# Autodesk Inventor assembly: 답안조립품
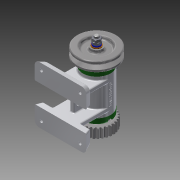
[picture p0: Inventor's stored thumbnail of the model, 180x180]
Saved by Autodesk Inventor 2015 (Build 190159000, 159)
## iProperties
Created: 2016-07
Part Number: 답안조립품
Document SubType Name: Assembly
Designer: owner
Author: owner
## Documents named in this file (16)
- C:\Users\owner\Documents\460707V1007\460707V1007\답안조립품.iam
- C:\Users\owner\Documents\460707V1007\460707V1007\답안본체.ipt
- C:\Users\owner\Documents\460707V1007\460707V1007\너트 M 8.ipt
- C:\Users\owner\Documents\460707V1007\460707V1007\베어링 15 x 32 x 9.ipt
- C:\Users\owner\Documents\460707V1007\460707V1007\스프링와셔 8.ipt
- C:\Users\owner\Documents\460707V1007\460707V1007\오일 실 15 25 7.ipt
- C:\Users\owner\Documents\460707V1007\460707V1007\와셔 8x17.ipt
- C:\Users\owner\Documents\460707V1007\460707V1007\커버.ipt
- C:\Users\owner\Documents\460707V1007\460707V1007\키 3 x 3 x 12.ipt
- C:\Users\owner\Documents\460707V1007\460707V1007\V벨트풀리.ipt
- C:\Users\owner\Documents\460707V1007\460707V1007\니플 M 6 x 0.75.ipt
- C:\Users\owner\Documents\460707V1007\460707V1007\볼트 M 6 x 8.ipt
- C:\Users\owner\Documents\460707V1007\460707V1007\스퍼기어.ipt
- C:\Users\owner\Documents\460707V1007\460707V1007\와셔 6x11.5.ipt
- C:\Users\owner\Documents\460707V1007\460707V1007\축.ipt
- C:\Users\owner\Documents\460707V1007\460707V1007\볼트 M4 x 12.ipt
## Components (11 placed, 3 different names)
1. KS B 2023 6002 - 15 x 32 x 9:1
2. KS B 2023 6002 - 15 x 32 x 9:2
3. V벨트풀리:1 — 각도:3
4. ISO 4762 M4 x 12:1
5. ISO 4762 M4 x 12:3
6. ISO 4762 M4 x 12:4
7. ISO 4762 M4 x 12:5
8. ISO 4762 M4 x 12:2
9. ISO 4762 M4 x 12:6
10. ISO 4762 M4 x 12:7
11. ISO 4762 M4 x 12:8
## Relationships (1: Angle 1)
- 각도:3 [Angle]: V벨트풀리:1
